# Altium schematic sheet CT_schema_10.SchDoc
size 281 x 153 mm
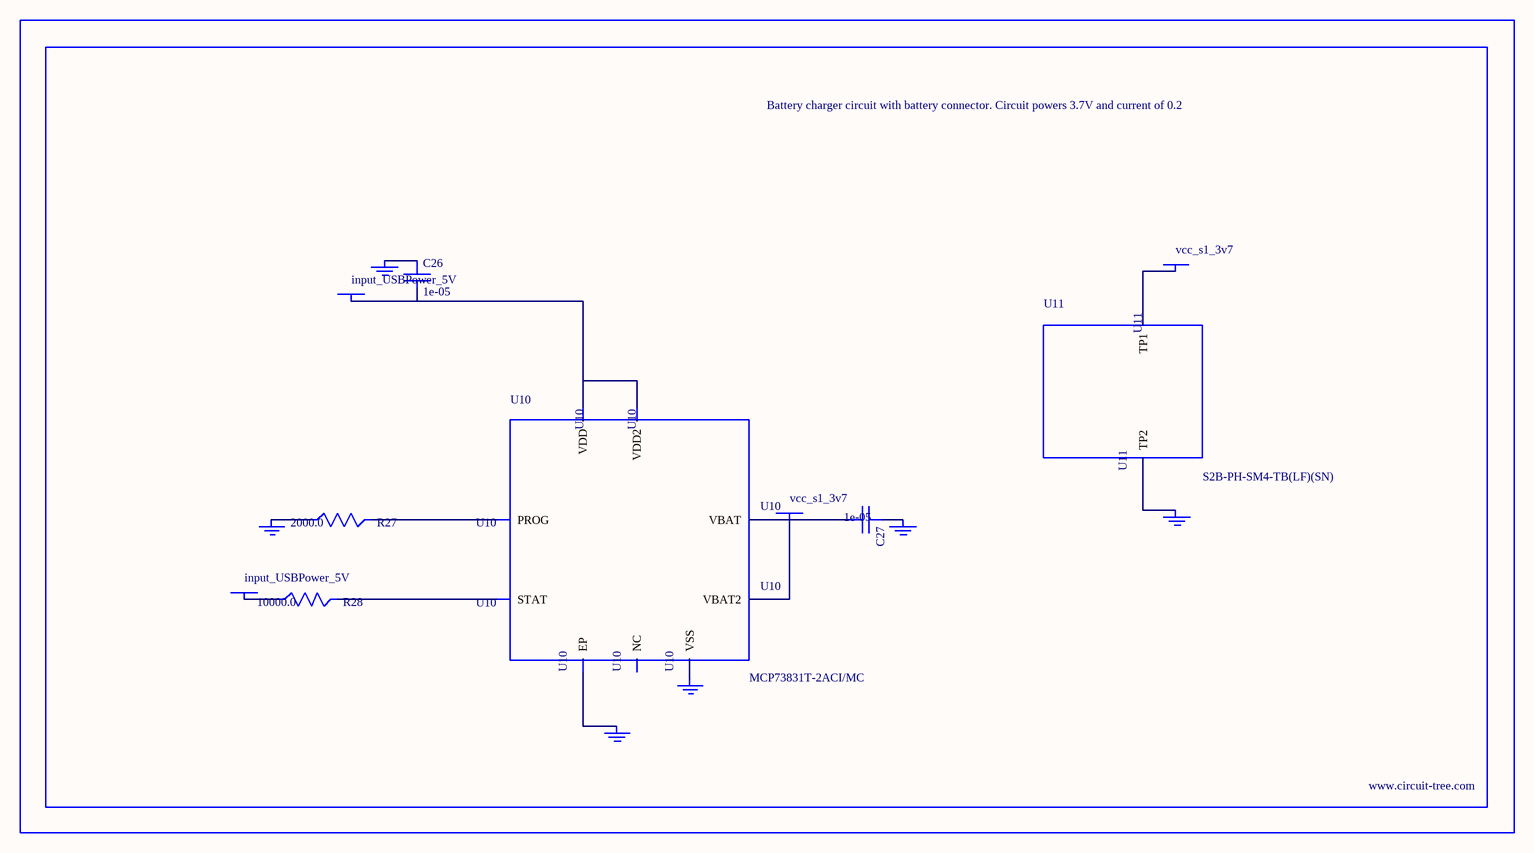
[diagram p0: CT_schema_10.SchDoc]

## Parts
BORDER9  (no value)
C26  1e-05  [C1206]
C27  1e-05  [C1206]
GND_INSTANCE_9_0  (no value)
GND_INSTANCE_9_1  (no value)
GND_INSTANCE_9_2  (no value)
GND_INSTANCE_9_3  (no value)
GND_INSTANCE_9_4  (no value)
GND_INSTANCE_9_5  (no value)
POWER_INSTANCE_9_0  input_USBPower_5V
POWER_INSTANCE_9_1  input_USBPower_5V
POWER_INSTANCE_9_2  vcc_s1_3v7
POWER_INSTANCE_9_3  vcc_s1_3v7
R27  2000.0  [R0603]
R28  10000.0  [R0603]
U10  MCP73831T-2ACI/MC  [DFN8_2X3MC]
U11  S2B-PH-SM4-TB(LF)(SN)  [JST-2-SMD]

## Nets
NetC26_1: C26.1 GND_INSTANCE_9_0.0(GND)
NetC26_2: C26.2 POWER_INSTANCE_9_0.0(PWR) U10.1(VDD) U10.2(VDD2)
NetC27_1: C27.1 GND_INSTANCE_9_1.0(GND)
NetC27_2: C27.2 POWER_INSTANCE_9_2.0(PWR) U10.3(VBAT) U10.4(VBAT2)
NetGND_INSTANCE_9_2_0: GND_INSTANCE_9_2.0(GND) R27.1
NetGND_INSTANCE_9_3_0: GND_INSTANCE_9_3.0(GND) U10.9(EP)
NetGND_INSTANCE_9_4_0: GND_INSTANCE_9_4.0(GND) U10.6(VSS)
NetGND_INSTANCE_9_5_0: GND_INSTANCE_9_5.0(GND) U11.2(TP2)
NetPOWER_INSTANCE_9_1_0: POWER_INSTANCE_9_1.0(PWR) R28.1
NetPOWER_INSTANCE_9_3_0: POWER_INSTANCE_9_3.0(PWR) U11.1(TP1)
NetR27_2: R27.2 U10.8(PROG)
NetR28_2: R28.2 U10.5(STAT)

Not connected (* = marked no-connect by the designer): U10 7(NC)

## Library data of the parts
BORDER9 = BORDER_PAGE9
C26 C27 = C1206C106K3RACTU
GND_INSTANCE_9_0-GND_INSTANCE_9_5 = GND
POWER_INSTANCE_9_0-POWER_INSTANCE_9_3 = PWR
R27 = RC0603JR-072KL
R28 = RC0603JR-0710KL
